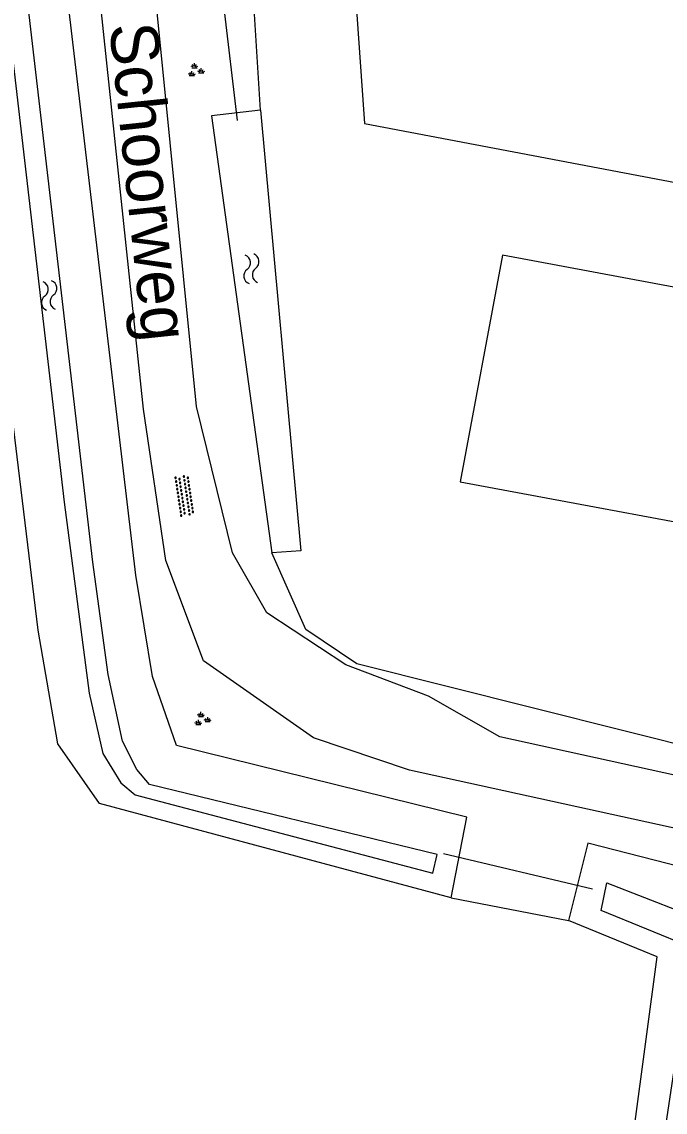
# Model space of a CAD drawing. Extents: x 124000 to 129000, y 395500 to 397503.
# Drawn here: x 125959.3 to 125992.9, y 395940.4 to 395997.4 of the extents above; entities that cross this region are included whole.
import ezdxf

# ---------------------------------------------------------------- set-up
doc = ezdxf.new("R2010")
doc.units = 0
for name, color, linetype in [('gg-afsc-draadraster', 7, 'Continuous'), ('gg-anno-openbare ruimte label', 7, 'Continuous'), ('gg-bbg-bijgebouw', 7, 'Continuous'), ('gg-knt-bronhoudergrens', 7, 'Continuous'), ('gg-knt-onverhard', 7, 'Continuous'), ('gg-kntw-bovenkant insteek waterloop', 7, 'Continuous'), ('gg-kntw-waterlijn', 7, 'Continuous'), ('gg-kwrk-duiker nz buis', 7, 'Continuous'), ('gt-grn-groengrens', 7, 'Continuous'), ('gt-symb-groenvak', 7, 'Continuous'), ('gt-symb-overige verharding', 7, 'Continuous'), ('gt-symb-watersymbool', 7, 'Continuous')]:
    doc.layers.add(name, color=color, linetype=linetype)

# ---------------------------------------------------------------- blocks, each defined once
blk = doc.blocks.new('gt0-WA')
at = {"layer": 'gt-symb-watersymbool'}
for centre, start, end in [((-0.323, 0.022), 28.0725, 151.9275), ((0.427, 0.422), 208.0725, 331.9275), ((-0.323, -0.428), 28.0725, 151.9275), ((0.427, -0.028), 208.0725, 331.9275)]:
    blk.add_arc(centre, 0.425, start, end, dxfattribs=at)
blk = doc.blocks.new('gt0-OVH')
at = {"layer": 'gt-symb-overige verharding'}
for points in [[(-0.972, 0.298), (-0.967, 0.308), (-0.965, 0.319), (-0.966, 0.33), (-0.971, 0.34), (-0.978, 0.348), (-0.988, 0.353), (-0.999, 0.355), (-1.01, 0.354), (-1.02, 0.349), (-1.028, 0.342), (-1.033, 0.332), (-1.035, 0.321), (-1.034, 0.31), (-1.029, 0.3), (-1.022, 0.292), (-1.012, 0.287), (-1.001, 0.285), (-0.99, 0.286), (-0.98, 0.291)], [(-0.872, 0.106), (-0.867, 0.116), (-0.865, 0.126), (-0.866, 0.137), (-0.871, 0.147), (-0.878, 0.156), (-0.888, 0.161), (-0.899, 0.163), (-0.91, 0.162), (-0.92, 0.157), (-0.928, 0.15), (-0.933, 0.14), (-0.935, 0.129), (-0.934, 0.118), (-0.929, 0.108), (-0.922, 0.1), (-0.912, 0.095), (-0.901, 0.092), (-0.89, 0.094), (-0.88, 0.098)], [(-0.772, 0.298), (-0.767, 0.308), (-0.765, 0.319), (-0.766, 0.33), (-0.771, 0.34), (-0.778, 0.348), (-0.788, 0.353), (-0.799, 0.355), (-0.81, 0.354), (-0.82, 0.349), (-0.828, 0.342), (-0.833, 0.332), (-0.835, 0.321), (-0.834, 0.31), (-0.829, 0.3), (-0.822, 0.292), (-0.812, 0.287), (-0.801, 0.285), (-0.79, 0.286), (-0.78, 0.291)], [(-0.672, 0.106), (-0.667, 0.116), (-0.665, 0.126), (-0.666, 0.137), (-0.671, 0.147), (-0.678, 0.156), (-0.688, 0.161), (-0.699, 0.163), (-0.71, 0.162), (-0.72, 0.157), (-0.728, 0.15), (-0.733, 0.14), (-0.735, 0.129), (-0.734, 0.118), (-0.729, 0.108), (-0.722, 0.1), (-0.712, 0.095), (-0.701, 0.092), (-0.69, 0.094), (-0.68, 0.098)], [(-0.572, 0.298), (-0.567, 0.308), (-0.565, 0.319), (-0.566, 0.33), (-0.571, 0.34), (-0.578, 0.348), (-0.588, 0.353), (-0.599, 0.355), (-0.61, 0.354), (-0.62, 0.349), (-0.628, 0.342), (-0.633, 0.332), (-0.635, 0.321), (-0.634, 0.31), (-0.629, 0.3), (-0.622, 0.292), (-0.612, 0.287), (-0.601, 0.285), (-0.59, 0.286), (-0.58, 0.291)], [(-0.472, 0.106), (-0.467, 0.116), (-0.465, 0.126), (-0.466, 0.137), (-0.471, 0.147), (-0.478, 0.156), (-0.488, 0.161), (-0.499, 0.163), (-0.51, 0.162), (-0.52, 0.157), (-0.528, 0.15), (-0.533, 0.14), (-0.535, 0.129), (-0.534, 0.118), (-0.529, 0.108), (-0.522, 0.1), (-0.512, 0.095), (-0.501, 0.092), (-0.49, 0.094), (-0.48, 0.098)], [(-0.372, 0.298), (-0.367, 0.308), (-0.365, 0.319), (-0.366, 0.33), (-0.371, 0.34), (-0.378, 0.348), (-0.388, 0.353), (-0.399, 0.355), (-0.41, 0.354), (-0.42, 0.349), (-0.428, 0.342), (-0.433, 0.332), (-0.435, 0.321), (-0.434, 0.31), (-0.429, 0.3), (-0.422, 0.292), (-0.412, 0.287), (-0.401, 0.285), (-0.39, 0.286), (-0.38, 0.291)], [(-0.272, 0.106), (-0.267, 0.116), (-0.265, 0.126), (-0.266, 0.137), (-0.271, 0.147), (-0.278, 0.156), (-0.288, 0.161), (-0.299, 0.163), (-0.31, 0.162), (-0.32, 0.157), (-0.328, 0.15), (-0.333, 0.14), (-0.335, 0.129), (-0.334, 0.118), (-0.329, 0.108), (-0.322, 0.1), (-0.312, 0.095), (-0.301, 0.092), (-0.29, 0.094), (-0.28, 0.098)], [(-0.172, 0.298), (-0.167, 0.308), (-0.165, 0.319), (-0.166, 0.33), (-0.171, 0.34), (-0.178, 0.348), (-0.188, 0.353), (-0.199, 0.355), (-0.21, 0.354), (-0.22, 0.349), (-0.228, 0.342), (-0.233, 0.332), (-0.235, 0.321), (-0.234, 0.31), (-0.229, 0.3), (-0.222, 0.292), (-0.212, 0.287), (-0.201, 0.285), (-0.19, 0.286), (-0.18, 0.291)], [(-0.072, 0.106), (-0.067, 0.116), (-0.065, 0.126), (-0.066, 0.137), (-0.071, 0.147), (-0.078, 0.156), (-0.088, 0.161), (-0.099, 0.163), (-0.11, 0.162), (-0.12, 0.157), (-0.128, 0.15), (-0.133, 0.14), (-0.135, 0.129), (-0.134, 0.118), (-0.129, 0.108), (-0.122, 0.1), (-0.112, 0.095), (-0.101, 0.092), (-0.09, 0.094), (-0.08, 0.098)], [(0.028, 0.298), (0.033, 0.308), (0.035, 0.319), (0.034, 0.33), (0.029, 0.34), (0.022, 0.348), (0.012, 0.353), (0.001, 0.355), (-0.01, 0.354), (-0.02, 0.349), (-0.028, 0.342), (-0.033, 0.332), (-0.035, 0.321), (-0.034, 0.31), (-0.029, 0.3), (-0.022, 0.292), (-0.012, 0.287), (-0.001, 0.285), (0.01, 0.286), (0.02, 0.291)], [(0.128, 0.106), (0.133, 0.116), (0.135, 0.126), (0.134, 0.137), (0.129, 0.147), (0.122, 0.156), (0.112, 0.161), (0.101, 0.163), (0.09, 0.162), (0.08, 0.157), (0.072, 0.15), (0.067, 0.14), (0.065, 0.129), (0.066, 0.118), (0.071, 0.108), (0.078, 0.1), (0.088, 0.095), (0.099, 0.092), (0.11, 0.094), (0.12, 0.098)], [(0.228, 0.298), (0.233, 0.308), (0.235, 0.319), (0.234, 0.33), (0.229, 0.34), (0.222, 0.348), (0.212, 0.353), (0.201, 0.355), (0.19, 0.354), (0.18, 0.349), (0.172, 0.342), (0.167, 0.332), (0.165, 0.321), (0.166, 0.31), (0.171, 0.3), (0.178, 0.292), (0.188, 0.287), (0.199, 0.285), (0.21, 0.286), (0.22, 0.291)], [(0.328, 0.106), (0.333, 0.116), (0.335, 0.126), (0.334, 0.137), (0.329, 0.147), (0.322, 0.156), (0.312, 0.161), (0.301, 0.163), (0.29, 0.162), (0.28, 0.157), (0.272, 0.15), (0.267, 0.14), (0.265, 0.129), (0.266, 0.118), (0.271, 0.108), (0.278, 0.1), (0.288, 0.095), (0.299, 0.092), (0.31, 0.094), (0.32, 0.098)], [(0.428, 0.298), (0.433, 0.308), (0.435, 0.319), (0.434, 0.33), (0.429, 0.34), (0.422, 0.348), (0.412, 0.353), (0.401, 0.355), (0.39, 0.354), (0.38, 0.349), (0.372, 0.342), (0.367, 0.332), (0.365, 0.321), (0.366, 0.31), (0.371, 0.3), (0.378, 0.292), (0.388, 0.287), (0.399, 0.285), (0.41, 0.286), (0.42, 0.291)], [(0.528, 0.106), (0.533, 0.116), (0.535, 0.126), (0.534, 0.137), (0.529, 0.147), (0.522, 0.156), (0.512, 0.161), (0.501, 0.163), (0.49, 0.162), (0.48, 0.157), (0.472, 0.15), (0.467, 0.14), (0.465, 0.129), (0.466, 0.118), (0.471, 0.108), (0.478, 0.1), (0.488, 0.095), (0.499, 0.092), (0.51, 0.094), (0.52, 0.098)], [(0.628, 0.298), (0.633, 0.308), (0.635, 0.319), (0.634, 0.33), (0.629, 0.34), (0.622, 0.348), (0.612, 0.353), (0.601, 0.355), (0.59, 0.354), (0.58, 0.349), (0.572, 0.342), (0.567, 0.332), (0.565, 0.321), (0.566, 0.31), (0.571, 0.3), (0.578, 0.292), (0.588, 0.287), (0.599, 0.285), (0.61, 0.286), (0.62, 0.291)], [(0.728, 0.106), (0.733, 0.116), (0.735, 0.126), (0.734, 0.137), (0.729, 0.147), (0.722, 0.156), (0.712, 0.161), (0.701, 0.163), (0.69, 0.162), (0.68, 0.157), (0.672, 0.15), (0.667, 0.14), (0.665, 0.129), (0.666, 0.118), (0.671, 0.108), (0.678, 0.1), (0.688, 0.095), (0.699, 0.092), (0.71, 0.094), (0.72, 0.098)], [(0.828, 0.298), (0.833, 0.308), (0.835, 0.319), (0.834, 0.33), (0.829, 0.34), (0.822, 0.348), (0.812, 0.353), (0.801, 0.355), (0.79, 0.354), (0.78, 0.349), (0.772, 0.342), (0.767, 0.332), (0.765, 0.321), (0.766, 0.31), (0.771, 0.3), (0.778, 0.292), (0.788, 0.287), (0.799, 0.285), (0.81, 0.286), (0.82, 0.291)], [(0.928, 0.106), (0.933, 0.116), (0.935, 0.126), (0.934, 0.137), (0.929, 0.147), (0.922, 0.156), (0.912, 0.161), (0.901, 0.163), (0.89, 0.162), (0.88, 0.157), (0.872, 0.15), (0.867, 0.14), (0.865, 0.129), (0.866, 0.118), (0.871, 0.108), (0.878, 0.1), (0.888, 0.095), (0.899, 0.092), (0.91, 0.094), (0.92, 0.098)], [(1.028, 0.298), (1.033, 0.308), (1.035, 0.319), (1.034, 0.33), (1.029, 0.34), (1.022, 0.348), (1.012, 0.353), (1.001, 0.355), (0.99, 0.354), (0.98, 0.349), (0.972, 0.342), (0.967, 0.332), (0.965, 0.321), (0.966, 0.31), (0.971, 0.3), (0.978, 0.292), (0.988, 0.287), (0.999, 0.285), (1.01, 0.286), (1.02, 0.291)], [(-0.972, -0.142), (-0.967, -0.132), (-0.965, -0.121), (-0.966, -0.11), (-0.971, -0.1), (-0.978, -0.092), (-0.988, -0.087), (-0.999, -0.085), (-1.01, -0.086), (-1.02, -0.091), (-1.028, -0.098), (-1.033, -0.108), (-1.035, -0.119), (-1.034, -0.13), (-1.029, -0.14), (-1.022, -0.148), (-1.012, -0.153), (-1.001, -0.155), (-0.99, -0.154), (-0.98, -0.149)], [(-0.872, -0.334), (-0.867, -0.324), (-0.865, -0.314), (-0.866, -0.303), (-0.871, -0.293), (-0.878, -0.284), (-0.888, -0.279), (-0.899, -0.277), (-0.91, -0.278), (-0.92, -0.283), (-0.928, -0.29), (-0.933, -0.3), (-0.935, -0.311), (-0.934, -0.322), (-0.929, -0.332), (-0.922, -0.34), (-0.912, -0.345), (-0.901, -0.348), (-0.89, -0.346), (-0.88, -0.342)], [(-0.772, -0.142), (-0.767, -0.132), (-0.765, -0.121), (-0.766, -0.11), (-0.771, -0.1), (-0.778, -0.092), (-0.788, -0.087), (-0.799, -0.085), (-0.81, -0.086), (-0.82, -0.091), (-0.828, -0.098), (-0.833, -0.108), (-0.835, -0.119), (-0.834, -0.13), (-0.829, -0.14), (-0.822, -0.148), (-0.812, -0.153), (-0.801, -0.155), (-0.79, -0.154), (-0.78, -0.149)], [(-0.672, -0.334), (-0.667, -0.324), (-0.665, -0.314), (-0.666, -0.303), (-0.671, -0.293), (-0.678, -0.284), (-0.688, -0.279), (-0.699, -0.277), (-0.71, -0.278), (-0.72, -0.283), (-0.728, -0.29), (-0.733, -0.3), (-0.735, -0.311), (-0.734, -0.322), (-0.729, -0.332), (-0.722, -0.34), (-0.712, -0.345), (-0.701, -0.348), (-0.69, -0.346), (-0.68, -0.342)], [(-0.572, -0.142), (-0.567, -0.132), (-0.565, -0.121), (-0.566, -0.11), (-0.571, -0.1), (-0.578, -0.092), (-0.588, -0.087), (-0.599, -0.085), (-0.61, -0.086), (-0.62, -0.091), (-0.628, -0.098), (-0.633, -0.108), (-0.635, -0.119), (-0.634, -0.13), (-0.629, -0.14), (-0.622, -0.148), (-0.612, -0.153), (-0.601, -0.155), (-0.59, -0.154), (-0.58, -0.149)], [(-0.472, -0.334), (-0.467, -0.324), (-0.465, -0.314), (-0.466, -0.303), (-0.471, -0.293), (-0.478, -0.284), (-0.488, -0.279), (-0.499, -0.277), (-0.51, -0.278), (-0.52, -0.283), (-0.528, -0.29), (-0.533, -0.3), (-0.535, -0.311), (-0.534, -0.322), (-0.529, -0.332), (-0.522, -0.34), (-0.512, -0.345), (-0.501, -0.348), (-0.49, -0.346), (-0.48, -0.342)], [(-0.372, -0.142), (-0.367, -0.132), (-0.365, -0.121), (-0.366, -0.11), (-0.371, -0.1), (-0.378, -0.092), (-0.388, -0.087), (-0.399, -0.085), (-0.41, -0.086), (-0.42, -0.091), (-0.428, -0.098), (-0.433, -0.108), (-0.435, -0.119), (-0.434, -0.13), (-0.429, -0.14), (-0.422, -0.148), (-0.412, -0.153), (-0.401, -0.155), (-0.39, -0.154), (-0.38, -0.149)], [(-0.272, -0.334), (-0.267, -0.324), (-0.265, -0.314), (-0.266, -0.303), (-0.271, -0.293), (-0.278, -0.284), (-0.288, -0.279), (-0.299, -0.277), (-0.31, -0.278), (-0.32, -0.283), (-0.328, -0.29), (-0.333, -0.3), (-0.335, -0.311), (-0.334, -0.322), (-0.329, -0.332), (-0.322, -0.34), (-0.312, -0.345), (-0.301, -0.348), (-0.29, -0.346), (-0.28, -0.342)], [(-0.172, -0.142), (-0.167, -0.132), (-0.165, -0.121), (-0.166, -0.11), (-0.171, -0.1), (-0.178, -0.092), (-0.188, -0.087), (-0.199, -0.085), (-0.21, -0.086), (-0.22, -0.091), (-0.228, -0.098), (-0.233, -0.108), (-0.235, -0.119), (-0.234, -0.13), (-0.229, -0.14), (-0.222, -0.148), (-0.212, -0.153), (-0.201, -0.155), (-0.19, -0.154), (-0.18, -0.149)], [(-0.072, -0.334), (-0.067, -0.324), (-0.065, -0.314), (-0.066, -0.303), (-0.071, -0.293), (-0.078, -0.284), (-0.088, -0.279), (-0.099, -0.277), (-0.11, -0.278), (-0.12, -0.283), (-0.128, -0.29), (-0.133, -0.3), (-0.135, -0.311), (-0.134, -0.322), (-0.129, -0.332), (-0.122, -0.34), (-0.112, -0.345), (-0.101, -0.348), (-0.09, -0.346), (-0.08, -0.342)], [(0.028, -0.142), (0.033, -0.132), (0.035, -0.121), (0.034, -0.11), (0.029, -0.1), (0.022, -0.092), (0.012, -0.087), (0.001, -0.085), (-0.01, -0.086), (-0.02, -0.091), (-0.028, -0.098), (-0.033, -0.108), (-0.035, -0.119), (-0.034, -0.13), (-0.029, -0.14), (-0.022, -0.148), (-0.012, -0.153), (-0.001, -0.155), (0.01, -0.154), (0.02, -0.149)], [(0.128, -0.334), (0.133, -0.324), (0.135, -0.314), (0.134, -0.303), (0.129, -0.293), (0.122, -0.284), (0.112, -0.279), (0.101, -0.277), (0.09, -0.278), (0.08, -0.283), (0.072, -0.29), (0.067, -0.3), (0.065, -0.311), (0.066, -0.322), (0.071, -0.332), (0.078, -0.34), (0.088, -0.345), (0.099, -0.348), (0.11, -0.346), (0.12, -0.342)], [(0.228, -0.142), (0.233, -0.132), (0.235, -0.121), (0.234, -0.11), (0.229, -0.1), (0.222, -0.092), (0.212, -0.087), (0.201, -0.085), (0.19, -0.086), (0.18, -0.091), (0.172, -0.098), (0.167, -0.108), (0.165, -0.119), (0.166, -0.13), (0.171, -0.14), (0.178, -0.148), (0.188, -0.153), (0.199, -0.155), (0.21, -0.154), (0.22, -0.149)], [(0.328, -0.334), (0.333, -0.324), (0.335, -0.314), (0.334, -0.303), (0.329, -0.293), (0.322, -0.284), (0.312, -0.279), (0.301, -0.277), (0.29, -0.278), (0.28, -0.283), (0.272, -0.29), (0.267, -0.3), (0.265, -0.311), (0.266, -0.322), (0.271, -0.332), (0.278, -0.34), (0.288, -0.345), (0.299, -0.348), (0.31, -0.346), (0.32, -0.342)], [(0.428, -0.142), (0.433, -0.132), (0.435, -0.121), (0.434, -0.11), (0.429, -0.1), (0.422, -0.092), (0.412, -0.087), (0.401, -0.085), (0.39, -0.086), (0.38, -0.091), (0.372, -0.098), (0.367, -0.108), (0.365, -0.119), (0.366, -0.13), (0.371, -0.14), (0.378, -0.148), (0.388, -0.153), (0.399, -0.155), (0.41, -0.154), (0.42, -0.149)], [(0.528, -0.334), (0.533, -0.324), (0.535, -0.314), (0.534, -0.303), (0.529, -0.293), (0.522, -0.284), (0.512, -0.279), (0.501, -0.277), (0.49, -0.278), (0.48, -0.283), (0.472, -0.29), (0.467, -0.3), (0.465, -0.311), (0.466, -0.322), (0.471, -0.332), (0.478, -0.34), (0.488, -0.345), (0.499, -0.348), (0.51, -0.346), (0.52, -0.342)], [(0.628, -0.142), (0.633, -0.132), (0.635, -0.121), (0.634, -0.11), (0.629, -0.1), (0.622, -0.092), (0.612, -0.087), (0.601, -0.085), (0.59, -0.086), (0.58, -0.091), (0.572, -0.098), (0.567, -0.108), (0.565, -0.119), (0.566, -0.13), (0.571, -0.14), (0.578, -0.148), (0.588, -0.153), (0.599, -0.155), (0.61, -0.154), (0.62, -0.149)], [(0.728, -0.334), (0.733, -0.324), (0.735, -0.314), (0.734, -0.303), (0.729, -0.293), (0.722, -0.284), (0.712, -0.279), (0.701, -0.277), (0.69, -0.278), (0.68, -0.283), (0.672, -0.29), (0.667, -0.3), (0.665, -0.311), (0.666, -0.322), (0.671, -0.332), (0.678, -0.34), (0.688, -0.345), (0.699, -0.348), (0.71, -0.346), (0.72, -0.342)], [(0.828, -0.142), (0.833, -0.132), (0.835, -0.121), (0.834, -0.11), (0.829, -0.1), (0.822, -0.092), (0.812, -0.087), (0.801, -0.085), (0.79, -0.086), (0.78, -0.091), (0.772, -0.098), (0.767, -0.108), (0.765, -0.119), (0.766, -0.13), (0.771, -0.14), (0.778, -0.148), (0.788, -0.153), (0.799, -0.155), (0.81, -0.154), (0.82, -0.149)], [(0.928, -0.334), (0.933, -0.324), (0.935, -0.314), (0.934, -0.303), (0.929, -0.293), (0.922, -0.284), (0.912, -0.279), (0.901, -0.277), (0.89, -0.278), (0.88, -0.283), (0.872, -0.29), (0.867, -0.3), (0.865, -0.311), (0.866, -0.322), (0.871, -0.332), (0.878, -0.34), (0.888, -0.345), (0.899, -0.348), (0.91, -0.346), (0.92, -0.342)], [(1.028, -0.142), (1.033, -0.132), (1.035, -0.121), (1.034, -0.11), (1.029, -0.1), (1.022, -0.092), (1.012, -0.087), (1.001, -0.085), (0.99, -0.086), (0.98, -0.091), (0.972, -0.098), (0.967, -0.108), (0.965, -0.119), (0.966, -0.13), (0.971, -0.14), (0.978, -0.148), (0.988, -0.153), (0.999, -0.155), (1.01, -0.154), (1.02, -0.149)]]:
    blk.add_lwpolyline(points, close=True, dxfattribs=at)
blk = doc.blocks.new('gt0-GRVAK')
at = {"layer": 'gt-symb-groenvak'}
for p, q in [((-0.11, 0.189), (-0.228, 0.24)), ((-0.182, 0.153), (0.088, 0.153)), ((-0.091, 0.211), (-0.156, 0.322)), ((-0.047, 0.214), (-0.047, 0.393)), ((-0.004, 0.211), (0.061, 0.322)), ((0.015, 0.189), (0.133, 0.24)), ((0.262, -0.052), (0.197, 0.059)), ((0.305, -0.049), (0.305, 0.13)), ((0.349, -0.052), (0.414, 0.059)), ((-0.245, -0.228), (-0.363, -0.177)), ((-0.318, -0.264), (-0.047, -0.264)), ((-0.226, -0.206), (-0.291, -0.095)), ((-0.183, -0.203), (-0.183, -0.024)), ((-0.139, -0.206), (-0.074, -0.095)), ((-0.12, -0.228), (-0.002, -0.177)), ((0.243, -0.074), (0.125, -0.023)), ((0.17, -0.11), (0.441, -0.11)), ((0.368, -0.074), (0.486, -0.023))]:
    blk.add_line(p, q, dxfattribs=at)

msp = doc.modelspace()

# ---------------------------------------------------------------- linework, layer by layer
at = {"layer": 'gg-afsc-draadraster'}
msp.add_lwpolyline([(126059.391, 395988.382), (126062.927, 396010.386), (126033.021, 396015.443), (126027.779, 396021.77), (125992.912, 396028.986), (125975.964, 396009.688), (125977.194, 395992.104), (126024.41, 395983.153), (126027.723, 395997.431), (126030.813, 395996.537), (126041.614, 395991.854), (126059.391, 395988.382)], dxfattribs=at)
at = {"layer": 'gg-bbg-bijgebouw'}
msp.add_lwpolyline([(126000, 395982.307), (125984.42, 395985.22), (125982.2, 395973.37), (126000, 395970.057)], dxfattribs=at)
at = {"layer": 'gg-knt-bronhoudergrens'}
msp.add_line((125981.73, 395951.62), (125987.87, 395950.43), dxfattribs=at)
at = {"layer": 'gg-knt-onverhard'}
for points in [[(126000, 395956.58), (125984.28, 395960.04), (125980.55, 395962.15), (125976.22, 395963.8), (125972.1, 395966.52), (125970.3, 395969.66), (125968.42, 395977.31), (125964.3, 396018.56), (125961.875, 396030.673)], [(126000, 395953.806), (125979.56, 395958.29), (125974.54, 395959.98), (125968.79, 395964.01), (125966.82, 395969.25), (125965.64, 395977.16), (125961.31, 396018.16), (125959.004, 396030.195)]]:
    msp.add_lwpolyline(points, dxfattribs=at)
at = {"layer": 'gg-kntw-bovenkant insteek waterloop'}
for points in [[(125981.73, 395951.62), (125963.35, 395956.54), (125961.17, 395959.66), (125960.14, 395965.61), (125952.63, 396027.5), (125950.12, 396035.12), (125920.85, 396105.23), (125911.54, 396128.66)], [(125981.73, 395951.62), (125982.55, 395955.83), (125967.37, 395959.58), (125966.11, 395963.19), (125965.25, 395968.48), (125957.966, 396030.006)], [(125971.759, 395992.803), (125969.203, 395992.511), (125972.362, 395969.658)], [(125971.759, 395992.803), (125973.87, 395969.752), (125972.362, 395969.658)], [(125997.194, 395947.978), (125997.64, 395950.91), (125994.45, 395953.05), (125988.87, 395954.48), (125987.87, 395950.43)], [(125990.7, 395935.08), (125992.5, 395948.52), (125987.87, 395950.43)]]:
    msp.add_lwpolyline(points, dxfattribs=at)
at = {"layer": 'gg-kntw-waterlijn'}
for points in [[(125981.006, 395953.872), (125965.967, 395957.545), (125965.301, 395958.325), (125964.543, 395959.806), (125963.795, 395963.293), (125962.994, 395969.171), (125956.289, 396026.724), (125954.951, 396032.619), (125934.155, 396083.617), (125917.103, 396126.419), (125915.354, 396126.538), (125924.145, 396104.824), (125948.384, 396046.09), (125953.93, 396032.089), (125955.124, 396027.121), (125961.506, 395972.299), (125962.805, 395962.319), (125963.519, 395959.157), (125964.458, 395957.62), (125965.216, 395956.992), (125980.779, 395952.908), (125981.006, 395953.872)], [(125986.218, 395888.628), (125984.937, 395888.875), (125991.042, 395926.891), (125994.341, 395948.999), (125989.566, 395950.953), (125989.877, 395952.399), (125995.78, 395950.091), (125988.83, 395904.833), (125986.218, 395888.628)]]:
    msp.add_lwpolyline(points, dxfattribs=at)
at = {"layer": 'gg-kwrk-duiker nz buis'}
for p, q in [((125970.561, 395992.258), (125969.846, 395998.283)), ((125989.112, 395952.069), (125981.336, 395953.911))]:
    msp.add_line(p, q, dxfattribs=at)
at = {"layer": 'gt-grn-groengrens'}
msp.add_line((125971.759, 395992.803), (125971.45, 395997.825), dxfattribs=at)
msp.add_lwpolyline([(126022.658, 395953.431), (126000, 395958.019), (125976.807, 395963.854), (125974.126, 395965.64), (125972.362, 395969.658)], dxfattribs=at)

# ---------------------------------------------------------------- block references
at = {"layer": 'gt-symb-groenvak'}
for p in [(125968.357, 395994.87), (125968.697, 395960.938)]:
    msp.add_blockref('gt0-GRVAK', p, dxfattribs=at)
at = {"layer": 'gt-symb-overige verharding', "rotation": 98.51093419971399}
msp.add_blockref('gt0-OVH', (125967.787, 395972.637), dxfattribs=at)
at = {"layer": 'gt-symb-watersymbool'}
for p, rotation in [((125971.283, 395984.558), -82.12907950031), ((125960.709, 395983.161), -82.8749836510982)]:
    msp.add_blockref('gt0-WA', p, dxfattribs=dict(at, rotation=rotation))

# ---------------------------------------------------------------- texts
at = {"layer": 'gg-anno-openbare ruimte label'}
msp.add_text('Schoorweg', height=2.5, rotation=276, dxfattribs=at).set_placement((125963.851, 395997.253))

doc.saveas('drawing.dxf')
